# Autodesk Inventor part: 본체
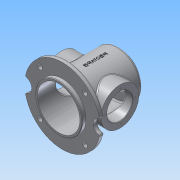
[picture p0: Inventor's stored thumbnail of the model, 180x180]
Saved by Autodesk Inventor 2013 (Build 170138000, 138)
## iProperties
Created: 2018-04
Part Number: 본체
Material: 알루미늄 6061
Document SubType Name: Modeling
Designer: Administrator
Density: 2.71 g/cm^3
Mass: 1151.24 g
Surface Area: 1200.36 cm^2
Volume: 424.812 cm^3
Author: Administrator
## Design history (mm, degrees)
sketch "스케치1"
  geometry: C1 r 50 at (0, 0); 1 further point
  constraints: 1 centre point, 1 coincident
  dimensions: "d1" = 100 diameter of C1
extrude "돌출1" new body sketch "스케치1" distance "d2" = 128; taper "d3" = 0 deg
hole "구멍1" diameter "d6" = 90; stored, may be unused: countersink angle "d10" = 90 deg, drill point angle "d12" = 0 deg; dims "d4" = 10, "d5" = 10, "d7" = 6, "d8" = 4, "d9" = 2, "d11" = 120
node "작업 평면1"
sketch "스케치2"
  geometry: C1 r 80 at (0, 0); C2 r 50 at (0, 0) reference; 1 further point
  constraints: 1 centre point, 1 coincident
  dimensions: "d14" = 160 diameter of C1
extrude "돌출2" join sketch "스케치2" distance "d15" = 10; taper "d16" = 0 deg
sketch "스케치3"
  geometry: C1 r 50 at (0, 0) reference; C2 r 15 at (-80, 0); C3 r 15 at (80, 0); A1 r 80 centre (0, 0) between (-80, 0) and (80, 0) reference
  constraints: 2 centre point, 2 horizontal alignment, 2 point on circle
  dimensions: "d17" = 30 diameter of C2; "d18" = 30 diameter of C3
extrude "돌출3" cut sketch "스케치3" stored distance "d19" = 10; taper "d20" = 0 deg
sketch "스케치4" dims "d21" = 135
  geometry: L1 (0, 50)-(0, 0); L2 (0, 0)-(-47.73, 47.73); C1 r 5 at (-47.73, 47.73); A1 r 80 centre (0, 0) between (78.594, 14.934) and (-78.594, 14.934) reference; 1 further point
  constraints: 4 end point, 2 coincident, 1 centre point, 1 vertical, 1 vertical alignment, 4 other
  dimensions: "d22" = 45 deg angle of L2 L1; "d24" = 10 diameter of C1
extrude "돌출4" cut sketch "스케치4" stored distance "d25" = 10; taper "d26" = 0 deg
node "작업 평면2"
sketch "스케치5"
  geometry: L1 (8, -14.934)-(8, -80) reference; C1 r 40 at (68, 0); 1 further point
  constraints: 1 centre point, 1 horizontal alignment
  dimensions: "d31" = 80 diameter of C1; "d33" = 60 distance from line of L1 C1.centre
extrude "돌출5" join sketch "스케치5" stored distance "d34" = 10; taper "d35" = 0 deg
sketch "스케치6"
  geometry: C1 r 40 at (0, 0) reference; 2 further points
  constraints: 1 coincident
hole "구멍2" sketch "스케치6" at (0, 0) diameter "d36" = 54; stored, may be unused: countersink angle "d40" = 90 deg, drill point angle "d42" = 0 deg; dims "d37" = 6, "d38" = 4, "d39" = 2, "d41" = 120
sketch "스케치7"
  geometry: C1 r 27 at (0, 0) reference; 2 further points
  constraints: 1 vertical alignment
  dimensions: "d43" = 32.5 distance of point (0, 32.5) C1.centre
hole "구멍3" sketch "스케치7" at (0, 32.5) diameter "d44" = 3.242; stored, may be unused: countersink angle "d48" = 90 deg, drill point angle "d50" = 118 deg; dims "d45" = 8, "d46" = 4, "d47" = 2, "d49" = 10
sketch "스케치8"
  geometry: C1 r 50 at (0, 0) reference; C2 r 40 at (0, 0)
  constraints: 1 centre point, 1 coincident
  dimensions: "d54" = 80 diameter of C2
extrude "돌출6" join sketch "스케치8" distance "d55" = 5; taper "d56" = 0 deg
hole "구멍4" diameter "d59" = 54; stored, may be unused: countersink angle "d63" = 90 deg, drill point angle "d65" = 118 deg; dims "d57" = 10, "d58" = 10, "d60" = 8, "d61" = 4, "d62" = 2, "d64" = 10
sketch "스케치9"
  geometry: C1 r 27 at (0, 0) reference; 1 further point
  constraints: 1 vertical alignment
  dimensions: "d66" = 32.5 distance of C1.centre point (0, 32.5)
hole "구멍5" sketch "스케치9" at (0, 32.5) diameter "d67" = 3.242; stored, may be unused: countersink angle "d71" = 90 deg, drill point angle "d73" = 118 deg; dims "d68" = 8, "d69" = 4, "d70" = 2, "d72" = 10
node "작업 평면3"
sketch "스케치10"
  geometry: L1 (-78.594, 8)-(78.594, 8) reference; 2 further points
  constraints: 1 vertical alignment, 1 other
  dimensions: "d92" = 70 distance from line of point (0, 78) L1
feature "엠보싱1" sketch "스케치10" dims "d2" = 128, "d79" = 0.5, "d80" = 0
fillet "모깎기1" dims "d81" = 5
fillet "모깎기2" dims "d82" = 3
fillet "모깎기3" dims "d83" = 3
fillet "모깎기4" dims "d84" = 3
fillet "모깎기5" dims "d85" = 3
chamfer "모따기1" distance "d86" = 1; stored, may be unused: second distance "d87" = 2, angle "d88" = 45 deg
chamfer "모따기2" distance "d89" = 1; stored, may be unused: second distance "d90" = 2, angle "d91" = 45 deg
node "솔리드1"
pattern_circular "원형 패턴1" dims angle "d28" = 360 deg
pattern_circular "원형 패턴2" dims angle "d52" = 360 deg
mirror "대칭1"
pattern_circular "원형 패턴3" dims angle "d75" = 360 deg
other parameters: "d30" = 62
